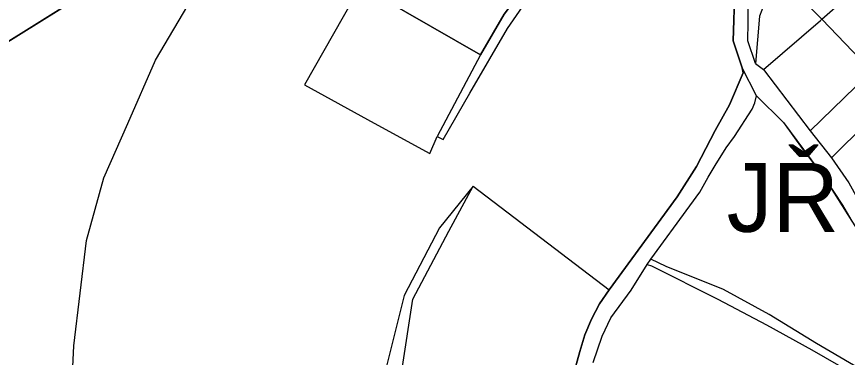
# Model space of a CAD drawing. Extents: x -706771 to -698463, y -971709 to -967107.
# Drawn here: x -702363 to -701879.1, y -969569.7 to -969371.5 of the extents above; entities that cross this region are included whole.
import ezdxf

# ---------------------------------------------------------------- set-up
doc = ezdxf.new("R2010")
doc.units = 0
for name, color, linetype in [('_hranice krajinny raz ochrana chrakteru zástavby KR2', 7, 'Continuous'), ('_KRAJINNY OKRSEK', 7, 'Continuous'), ('KN_Hranice_parcel', 7, 'Continuous'), ('Prvky nelesní zeleně_dominantní aleje', 7, 'Continuous')]:
    doc.layers.add(name, color=color, linetype=linetype)

msp = doc.modelspace()

# ---------------------------------------------------------------- linework, layer by layer
at = {"layer": '_hranice krajinny raz ochrana chrakteru zástavby KR2'}
for p, q in [((-702373.81, -969389.56), (-702312.9, -969351.61)), ((-702162.49, -969353.62), (-702092.89, -969393.76)), ((-701944.78, -969355.1), (-701945.67, -969385.53)), ((-702092.89, -969393.76), (-702078.97, -969369.97)), ((-701945.67, -969385.53), (-701940.32, -969401.31)), ((-701940.32, -969401.31), (-701939.92, -969404.18)), ((-701939.92, -969404.18), (-701947.78, -969422.7)), ((-701947.78, -969422.7), (-701956.07, -969437.75)), ((-701956.07, -969437.75), (-701967.1, -969458.59)), ((-701967.1, -969458.59), (-701978.18, -969476.28)), ((-701978.18, -969476.28), (-702017.8, -969530.34)), ((-702017.8, -969530.34), (-702023.43, -969538.6)), ((-702023.43, -969538.6), (-702028.11, -969547.45)), ((-702028.11, -969547.45), (-702032.09, -969556.62)), ((-702032.09, -969556.62), (-702034.99, -969566.19)), ((-702034.99, -969566.19), (-702040.25, -969585.03))]:
    msp.add_line(p, q, dxfattribs=at)
at = {"layer": '_KRAJINNY OKRSEK'}
for p, q in [((-702312.9, -969351.61), (-702373.81, -969389.56)), ((-702092.89, -969393.76), (-702162.49, -969353.62)), ((-702162.49, -969353.62), (-702092.89, -969393.76)), ((-701944.78, -969355.1), (-701945.67, -969385.53)), ((-701940.32, -969401.31), (-701945.67, -969385.53)), ((-701945.67, -969385.53), (-701940.32, -969401.31)), ((-701939.92, -969404.18), (-701940.32, -969401.31)), ((-701940.32, -969401.31), (-701939.92, -969404.18)), ((-701947.78, -969422.7), (-701939.92, -969404.18)), ((-701939.92, -969404.18), (-701947.78, -969422.7)), ((-702017.8, -969530.34), (-701978.18, -969476.28)), ((-702023.43, -969538.6), (-702028.11, -969547.45)), ((-702028.11, -969547.45), (-702032.09, -969556.62)), ((-702034.99, -969566.19), (-702032.09, -969556.62)), ((-702032.09, -969556.62), (-702034.99, -969566.19)), ((-702040.25, -969585.03), (-702034.99, -969566.19)), ((-702034.99, -969566.19), (-702040.25, -969585.03))]:
    msp.add_line(p, q, dxfattribs=at)
for points in [[(-702437.44, -969424.16), (-702436.17, -969412.4), (-702373.81, -969389.56), (-702312.9, -969351.61), (-702321.79, -969295.31)], [(-701945.67, -969385.53), (-701944.78, -969355.1), (-701943.32, -969351.07), (-701954.79, -969347.44)], [(-702063.86, -969349.8), (-702078.97, -969369.97), (-702092.89, -969393.76)], [(-702092.89, -969393.76), (-702078.97, -969369.97), (-702063.86, -969349.8)], [(-701978.18, -969476.28), (-701967.1, -969458.59), (-701956.07, -969437.75), (-701947.78, -969422.7)], [(-701947.78, -969422.7), (-701956.07, -969437.75), (-701967.1, -969458.59), (-701978.18, -969476.28)], [(-701978.18, -969476.28), (-702017.8, -969530.34), (-702023.43, -969538.6)], [(-702032.09, -969556.62), (-702028.11, -969547.45), (-702023.43, -969538.6), (-702017.8, -969530.34)]]:
    msp.add_lwpolyline(points, dxfattribs=at)
at = {"layer": 'KN_Hranice_parcel'}
for p, q in [((-701920.8, -969346.58), (-701894, -969373.01)), ((-701894, -969373.01), (-701871.41, -969396.45)), ((-701932.15, -969417.65), (-701940.32, -969401.31)), ((-701932.74, -969398.74), (-701928.08, -969402.31)), ((-701928.08, -969402.31), (-701900.8, -969437.89)), ((-701900.8, -969437.89), (-701865.37, -969403.37)), ((-701888.47, -969453.58), (-701852.29, -969417.71)), ((-701900.8, -969437.89), (-701888.47, -969453.58)), ((-702097.1, -969470.03), (-702017.8, -969530.34)), ((-701995.65, -969515.75), (-701993.59, -969512.52))]:
    msp.add_line(p, q, dxfattribs=at)
for points in [[(-702315.68, -969831.21), (-702324.6, -969781.95), (-702329.65, -969731.97), (-702334.63, -969669.7), (-702329.59, -969562.96), (-702322.24, -969501.76), (-702312.21, -969465.19), (-702298.26, -969433.58), (-702282.03, -969396.82), (-702260.72, -969360.62), (-702223.18, -969296.81), (-702198.98, -969235.34), (-702196.75, -969232.84)], [(-702127.01, -969291.52), (-702148.52, -969329.16), (-702172.73, -969371.54), (-702195.38, -969411.18), (-702154.68, -969433.43), (-702122.25, -969451.16), (-702118.01, -969441.22)], [(-701932.74, -969398.74), (-701937.17, -969385.64), (-701936.96, -969374.67), (-701936.79, -969358), (-701933.46, -969348.57), (-701927.59, -969340.48), (-701922.96, -969336.01)], [(-701920.8, -969346.58), (-701930.27, -969371.16), (-701932.74, -969398.74)], [(-702063.86, -969349.8), (-702078.97, -969369.97), (-702092.89, -969393.76), (-702118.01, -969441.22)], [(-702118.01, -969441.22), (-702114.56, -969442.93), (-702098.94, -969415.99), (-702077, -969378.3), (-702063.07, -969358.04), (-702058.32, -969349.92)], [(-701943.32, -969351.07), (-701944.78, -969355.1), (-701945.67, -969385.53), (-701940.32, -969401.31)], [(-701894, -969373.01), (-701876.87, -969357.83), (-701866.19, -969348.55)], [(-701928.08, -969402.31), (-701894.79, -969373.78), (-701894, -969373.01)], [(-701940.32, -969401.31), (-701939.92, -969404.18), (-701947.78, -969422.7), (-701956.07, -969437.75), (-701967.1, -969458.59), (-701978.18, -969476.28), (-702017.8, -969530.34)], [(-701993.59, -969512.52), (-701970.92, -969481.6), (-701965.01, -969473.53), (-701960.15, -969464.79), (-701956.15, -969458.01), (-701949.77, -969447.82), (-701944.94, -969441.28), (-701934.66, -969425.28), (-701932.95, -969421.58), (-701932.15, -969417.65)], [(-701932.15, -969417.65), (-701916.27, -969433.11), (-701905.5, -969448.18), (-701892.43, -969465.33), (-701881.94, -969481.12), (-701876.57, -969490.41), (-701870.6, -969499.82), (-701861.62, -969514.7), (-701845.58, -969545.8), (-701835.67, -969562.49), (-701832.77, -969566.66)], [(-701888.47, -969453.58), (-701878.24, -969468.09), (-701869.12, -969484.61)], [(-702097.1, -969470.03), (-702116.75, -969494.26), (-702137.27, -969533.76), (-702147.84, -969575.6), (-702156.54, -969611.5), (-702160.51, -969640.21), (-702163.62, -969652.44), (-702163.42, -969673.85)], [(-702152.56, -969671.8), (-702149.36, -969645.17), (-702135.92, -969621.52), (-702138.55, -969577.44), (-702132.23, -969535.81), (-702111.29, -969496.21), (-702097.1, -969470.03)], [(-701995.65, -969515.75), (-701993.25, -969516.41), (-701954.55, -969535.79), (-701926.32, -969550.74), (-701899.89, -969565.38), (-701876.49, -969578.7), (-701864.09, -969596.13), (-701864.19, -969590.02), (-701864.35, -969580.78), (-701897.13, -969561.65), (-701924.65, -969544.68), (-701951.28, -969530.25), (-701984.64, -969516.77), (-701993.59, -969512.52)], [(-702027.16, -969572.69), (-702021.87, -969557.38), (-702016.82, -969546.71), (-702005.09, -969530.56), (-701995.65, -969515.75)], [(-702017.8, -969530.34), (-702023.43, -969538.6), (-702028.11, -969547.45), (-702032.09, -969556.62), (-702034.99, -969566.19), (-702040.25, -969585.03), (-702043.56, -969594.47), (-702051.47, -969611.01)]]:
    msp.add_lwpolyline(points, dxfattribs=at)
at = {"layer": 'Prvky nelesní zeleně_dominantní aleje'}
msp.add_lwpolyline([(-701916.27, -969433.11), (-701892.43, -969465.33), (-701876.57, -969490.41)], dxfattribs=at)

# ---------------------------------------------------------------- texts
msp.add_text('JŘ', height=40, dxfattribs=at).set_placement((-701949.45, -969496.66))

doc.saveas('drawing.dxf')
